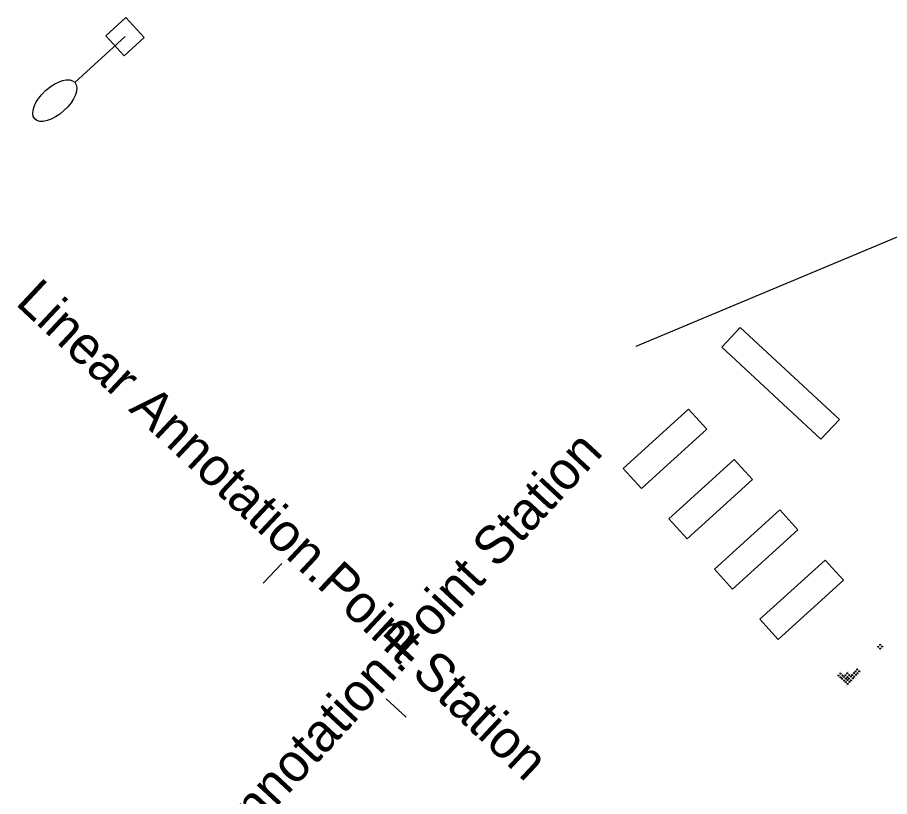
# Model space of a CAD drawing. Extents: x 1470334 to 1481646, y 379063 to 388330.
# Drawn here: x 1480147.6 to 1480211.9, y 379413 to 379470.4 of the extents above; entities that cross this region are included whole.
import ezdxf

# ---------------------------------------------------------------- set-up
doc = ezdxf.new("R2010")
doc.units = 0
for name, color, linetype in [('Default', 7, 'Continuous'), ('SG_X_Poles', 7, 'Continuous'), ('SV_X_Random_Point', 7, 'Continuous'), ('UT_X_Misc_Cells', 7, 'Continuous'), ('UT_X_Unknown_Cells', 7, 'Continuous'), ('UT_X_Water_Cells', 7, 'Continuous')]:
    doc.layers.add(name, color=color, linetype=linetype)

msp = doc.modelspace()

# ---------------------------------------------------------------- linework, layer by layer
at = {"layer": 'Default'}
for p, q in [((1480165.698, 379428.717), (1480167.065, 379430.177)), ((1480165.698, 379428.717), (1480167.065, 379430.177)), ((1480176.235, 379418.852), (1480174.768, 379420.212)), ((1480176.235, 379418.852), (1480174.768, 379420.212))]:
    msp.add_line(p, q, dxfattribs=at)
at = {"layer": 'SG_X_Poles'}
msp.add_line((1480155.523, 379468.979), (1480151.825, 379465.613), dxfattribs=at)
msp.add_lwpolyline([(1480156.935, 379468.912), (1480155.456, 379467.566), (1480154.11, 379469.045), (1480155.589, 379470.392)], close=True, dxfattribs=at)
msp.add_ellipse((1480150.346, 379464.268), major_axis=(-1.479, -1.346), ratio=0.5, dxfattribs=at)
at = {"layer": 'SV_X_Random_Point'}
msp.add_lwpolyline([(1480200.858, 379447.565), (1480208.158, 379440.787), (1480206.797, 379439.322), (1480199.497, 379446.1)], close=True, dxfattribs=at)
at = {"layer": 'UT_X_Misc_Cells'}
for points in [[(1480197.055, 379441.545), (1480198.397, 379440.063), (1480193.58, 379435.699), (1480192.238, 379437.181)], [(1480200.412, 379437.839), (1480201.754, 379436.357), (1480196.937, 379431.993), (1480195.594, 379433.475)], [(1480203.769, 379434.134), (1480205.111, 379432.651), (1480200.294, 379428.287), (1480198.951, 379429.77)], [(1480207.126, 379430.428), (1480208.468, 379428.946), (1480203.651, 379424.582), (1480202.308, 379426.064)]]:
    msp.add_lwpolyline(points, close=True, dxfattribs=at)
at = {"layer": 'UT_X_Unknown_Cells'}
for p, q in [((1480211.028, 379424.046), (1480211.028, 379424.046)), ((1480211.161, 379424.189), (1480211.161, 379424.189)), ((1480211.305, 379424.057), (1480211.305, 379424.057)), ((1480211.421, 379423.949), (1480211.421, 379423.949)), ((1480210.921, 379423.929), (1480210.921, 379423.929)), ((1480211.065, 379423.796), (1480211.065, 379423.796)), ((1480211.172, 379423.913), (1480211.172, 379423.913)), ((1480211.181, 379423.689), (1480211.181, 379423.689)), ((1480211.288, 379423.805), (1480211.288, 379423.805)), ((1480207.99, 379422.03), (1480207.99, 379422.03)), ((1480208.123, 379422.174), (1480208.123, 379422.174)), ((1480208.23, 379422.291), (1480208.23, 379422.291)), ((1480208.239, 379422.067), (1480208.239, 379422.067)), ((1480208.346, 379422.183), (1480208.346, 379422.183)), ((1480208.49, 379422.051), (1480208.49, 379422.051)), ((1480208.49, 379422.051), (1480208.49, 379422.051)), ((1480208.49, 379422.051), (1480208.49, 379422.051)), ((1480208.623, 379422.194), (1480208.623, 379422.194)), ((1480208.73, 379422.311), (1480208.73, 379422.311)), ((1480208.739, 379422.087), (1480208.739, 379422.087)), ((1480208.847, 379422.203), (1480208.847, 379422.203)), ((1480208.991, 379422.071), (1480208.991, 379422.071)), ((1480209.24, 379422.107), (1480209.24, 379422.107)), ((1480209.24, 379422.107), (1480209.24, 379422.107)), ((1480209.347, 379422.224), (1480209.347, 379422.224)), ((1480209.48, 379422.368), (1480209.48, 379422.368)), ((1480209.491, 379422.091), (1480209.491, 379422.091)), ((1480209.624, 379422.235), (1480209.624, 379422.235)), ((1480209.74, 379422.127), (1480209.74, 379422.127)), ((1480208.106, 379421.923), (1480208.106, 379421.923)), ((1480208.25, 379421.79), (1480208.25, 379421.79)), ((1480208.25, 379421.79), (1480208.25, 379421.79)), ((1480208.367, 379421.683), (1480208.367, 379421.683)), ((1480208.383, 379421.934), (1480208.383, 379421.934)), ((1480208.383, 379421.934), (1480208.383, 379421.934)), ((1480208.499, 379421.827), (1480208.499, 379421.827)), ((1480208.51, 379421.55), (1480208.51, 379421.55)), ((1480208.607, 379421.943), (1480208.607, 379421.943)), ((1480208.607, 379421.943), (1480208.607, 379421.943)), ((1480208.627, 379421.443), (1480208.627, 379421.443)), ((1480208.643, 379421.694), (1480208.643, 379421.694)), ((1480208.751, 379421.81), (1480208.751, 379421.81)), ((1480208.751, 379421.81), (1480208.751, 379421.81)), ((1480208.76, 379421.587), (1480208.76, 379421.587)), ((1480208.76, 379421.587), (1480208.76, 379421.587)), ((1480208.867, 379421.703), (1480208.867, 379421.703)), ((1480208.883, 379421.954), (1480208.883, 379421.954)), ((1480208.904, 379421.454), (1480208.904, 379421.454)), ((1480208.904, 379421.454), (1480208.904, 379421.454)), ((1480209, 379421.847), (1480209, 379421.847)), ((1480209, 379421.847), (1480209, 379421.847)), ((1480209.011, 379421.57), (1480209.011, 379421.57)), ((1480209.107, 379421.963), (1480209.107, 379421.963)), ((1480209.127, 379421.463), (1480209.127, 379421.463)), ((1480209.144, 379421.714), (1480209.144, 379421.714)), ((1480209.144, 379421.714), (1480209.144, 379421.714)), ((1480209.251, 379421.831), (1480209.251, 379421.831)), ((1480209.26, 379421.607), (1480209.26, 379421.607)), ((1480209.26, 379421.607), (1480209.26, 379421.607)), ((1480209.367, 379421.723), (1480209.367, 379421.723)), ((1480209.384, 379421.974), (1480209.384, 379421.974)), ((1480209.384, 379421.974), (1480209.384, 379421.974)), ((1480209.5, 379421.867), (1480209.5, 379421.867)), ((1480209.5, 379421.867), (1480209.5, 379421.867)), ((1480209.607, 379421.983), (1480209.607, 379421.983)), ((1480208.519, 379421.326), (1480208.519, 379421.326)), ((1480208.663, 379421.194), (1480208.663, 379421.194)), ((1480208.771, 379421.31), (1480208.771, 379421.31)), ((1480208.78, 379421.086), (1480208.78, 379421.086)), ((1480208.887, 379421.203), (1480208.887, 379421.203)), ((1480209.02, 379421.347), (1480209.02, 379421.347)), ((1480209.02, 379421.347), (1480209.02, 379421.347))]:
    msp.add_line(p, q, dxfattribs=at)
for centre, radius in [((1480211.028, 379424.046), 0.0375), ((1480211.028, 379424.046), 0.0167), ((1480211.161, 379424.189), 0.0375), ((1480211.172, 379423.913), 0.0375), ((1480211.161, 379424.189), 0.0167), ((1480211.305, 379424.057), 0.0375), ((1480211.305, 379424.057), 0.0167), ((1480211.172, 379423.913), 0.0167), ((1480208.239, 379422.067), 0.0375), ((1480208.239, 379422.067), 0.0167), ((1480208.739, 379422.087), 0.0375), ((1480208.739, 379422.087), 0.0167), ((1480209.24, 379422.107), 0.0375), ((1480209.24, 379422.107), 0.0167), ((1480209.347, 379422.224), 0.0375), ((1480209.347, 379422.224), 0.0167), ((1480209.384, 379421.974), 0.0375), ((1480209.48, 379422.368), 0.0375), ((1480209.491, 379422.091), 0.0375), ((1480209.48, 379422.368), 0.0167), ((1480209.491, 379422.091), 0.0167), ((1480209.624, 379422.235), 0.0375), ((1480209.624, 379422.235), 0.0167), ((1480208.106, 379421.923), 0.0375), ((1480208.106, 379421.923), 0.0167), ((1480208.25, 379421.79), 0.0375), ((1480208.25, 379421.79), 0.0167), ((1480208.367, 379421.683), 0.0375), ((1480208.383, 379421.934), 0.0375), ((1480208.367, 379421.683), 0.0167), ((1480208.383, 379421.934), 0.0167), ((1480208.499, 379421.827), 0.0375), ((1480208.51, 379421.55), 0.0375), ((1480208.499, 379421.827), 0.0167), ((1480208.51, 379421.55), 0.0167), ((1480208.607, 379421.943), 0.0375), ((1480208.627, 379421.443), 0.0375), ((1480208.607, 379421.943), 0.0167), ((1480208.643, 379421.694), 0.0375), ((1480208.627, 379421.443), 0.0167), ((1480208.643, 379421.694), 0.0167), ((1480208.751, 379421.81), 0.0375), ((1480208.76, 379421.587), 0.0375), ((1480208.751, 379421.81), 0.0167), ((1480208.76, 379421.587), 0.0167), ((1480208.867, 379421.703), 0.0375), ((1480208.883, 379421.954), 0.0375), ((1480208.867, 379421.703), 0.0167), ((1480208.904, 379421.454), 0.0375), ((1480208.883, 379421.954), 0.0167), ((1480208.904, 379421.454), 0.0167), ((1480209, 379421.847), 0.0375), ((1480209.011, 379421.57), 0.0375), ((1480209, 379421.847), 0.0167), ((1480209.011, 379421.57), 0.0167), ((1480209.107, 379421.963), 0.0375), ((1480209.107, 379421.963), 0.0167), ((1480209.144, 379421.714), 0.0375), ((1480209.144, 379421.714), 0.0167), ((1480209.251, 379421.831), 0.0375), ((1480209.251, 379421.831), 0.0167), ((1480209.384, 379421.974), 0.0167), ((1480208.771, 379421.31), 0.0375), ((1480208.771, 379421.31), 0.0167)]:
    msp.add_circle(centre, radius, dxfattribs=at)
at = {"layer": 'UT_X_Water_Cells'}
msp.add_line((1480244.471, 379467.581), (1480193.153, 379446.168), dxfattribs=at)

# ---------------------------------------------------------------- texts
at = {"layer": 'Default'}
for rotation, p in [(316.88603, (1480147.37, 379449.301)), (316.88603, (1480147.37, 379449.301)), (47.15888, (1480155.738, 379400.426)), (47.15888, (1480155.738, 379400.426))]:
    msp.add_text('Linear Annotation.Point Station', height=2.8, rotation=rotation, dxfattribs=at).set_placement(p)

doc.saveas('drawing.dxf')
